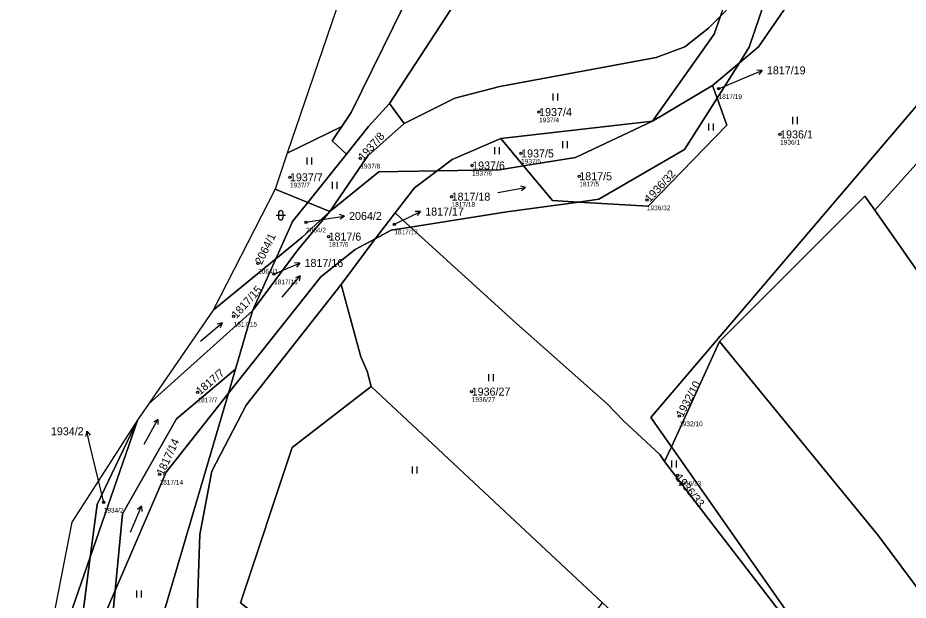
# Model space of a CAD drawing. Extents: x -762274 to -759271, y -1061928 to -1059060.
# Drawn here: x -761734.1 to -761545, y -1061234.6 to -1061110.9 of the extents above; entities that cross this region are included whole.
import ezdxf

# ---------------------------------------------------------------- set-up
doc = ezdxf.new("R2010")
doc.units = 0
for name, color, linetype in [('Definiční body', 7, 'Continuous'), ('Hranice parcel', 7, 'Continuous'), ('Parcelní čísla', 7, 'Continuous'), ('Polygon ku', 7, 'Continuous'), ('Polygon parcely', 7, 'Continuous'), ('Pop  PČ popisy', 7, 'Continuous'), ('Značky kultur', 7, 'Continuous')]:
    doc.layers.add(name, color=color, linetype=linetype)

msp = doc.modelspace()

# ---------------------------------------------------------------- linework, layer by layer
at = {"layer": 'Definiční body'}
for centre in [(-761585.27, -1061125.93), (-761623.37, -1061130.89), (-761572.19, -1061135.63), (-761627.19, -1061139.68), (-761661.33, -1061140.71), (-761637.59, -1061142.24), (-761676.28, -1061144.75), (-761614.84, -1061144.53), (-761641.96, -1061148.86), (-761600.48, -1061149.59), (-761672.86, -1061154.31), (-761654.12, -1061154.71), (-761668.09, -1061157.35), (-761683.05, -1061163.06), (-761679.65, -1061165.31), (-761688.24, -1061174.3), (-761695.91, -1061190.41), (-761637.69, -1061190.29), (-761593.62, -1061195.47), (-761703.97, -1061207.88), (-761593.93, -1061208.11), (-761715.84, -1061213.84)]:
    msp.add_circle(centre, 0.25, dxfattribs=at)
at = {"layer": 'Hranice parcel'}
for p, q in [((-761586.58, -1061125.23), (-761580.84, -1061120.41)), ((-761580.84, -1061120.41), (-761585.59, -1061127.93)), ((-761599.26, -1061132.85), (-761586.58, -1061125.23)), ((-761585.59, -1061127.93), (-761586.58, -1061125.23)), ((-761655.13, -1061129.07), (-761652.06, -1061133.33)), ((-761665.3, -1061133.96), (-761676.85, -1061139.64)), ((-761631.53, -1061136.51), (-761599.26, -1061132.85)), ((-761631.53, -1061136.51), (-761626.68, -1061142.32)), ((-761676.85, -1061139.64), (-761679.44, -1061147.26)), ((-761672.49, -1061150.08), (-761664.28, -1061139.8)), ((-761679.44, -1061147.26), (-761692.57, -1061172.96)), ((-761679.44, -1061147.26), (-761672.49, -1061150.08)), ((-761672.49, -1061150.08), (-761667.79, -1061151.98)), ((-761658.2, -1061157.81), (-761653.95, -1061152.32)), ((-761650.66, -1061155.32), (-761653.95, -1061152.32)), ((-761665.41, -1061167.51), (-761658.2, -1061157.81)), ((-761679.27, -1061162.04), (-761692.57, -1061172.96)), ((-761684.23, -1061173.13), (-761679.27, -1061162.04)), ((-761692.57, -1061172.96), (-761706.31, -1061192.95)), ((-761684.23, -1061173.13), (-761706.31, -1061192.95)), ((-761684.23, -1061173.13), (-761687.83, -1061185.51)), ((-761595.28, -1061201.99), (-761585.07, -1061179.66)), ((-761687.83, -1061185.51), (-761689.32, -1061190.63)), ((-761609.92, -1061235.2), (-761659.04, -1061189.22)), ((-761689.32, -1061190.63), (-761706.57, -1061248.98)), ((-761706.31, -1061192.95), (-761708.56, -1061196.23)), ((-761708.56, -1061196.23), (-761718.68, -1061225.44)), ((-761596.73, -1061205.16), (-761595.28, -1061201.99))]:
    msp.add_line(p, q, dxfattribs=at)
for points in [[(-761580.84, -1061120.41), (-761578.73, -1061117.07), (-761544.07, -1061015.12), (-761528.37, -1060979.24)], [(-761621.08, -1061016.62), (-761614.73, -1061021.75), (-761595.52, -1061037.25), (-761623.93, -1061081.12), (-761655.13, -1061129.07)], [(-761665.3, -1061133.96), (-761663.29, -1061130.97), (-761652.11, -1061108.27), (-761638.48, -1061080.32), (-761634.06, -1061069.21), (-761632.14, -1061061.04), (-761640.03, -1061045.99)], [(-761649.18, -1061061.93), (-761662.78, -1061098.32), (-761676.85, -1061139.64)], [(-761561.09, -1061083.11), (-761567.39, -1061101.46), (-761570.16, -1061107.4), (-761576.79, -1061117.01), (-761580.84, -1061120.41)], [(-761595.28, -1061201.99), (-761599.63, -1061195.76), (-761522.28, -1061104.91)], [(-761652.06, -1061133.33), (-761641.24, -1061127.91), (-761631.73, -1061125.43), (-761598.48, -1061119.29), (-761592.46, -1061117.03), (-761587.41, -1061113.06), (-761584.85, -1061110.5)], [(-761584.85, -1061110.5), (-761586.2, -1061114.32), (-761599.26, -1061132.85)], [(-761515.62, -1061111.21), (-761519.67, -1061115.58), (-761552.11, -1061151.74)], [(-761615.03, -1061150), (-761610.7, -1061149.4), (-761592.49, -1061138.84), (-761585.59, -1061127.93)], [(-761585.59, -1061127.93), (-761583.51, -1061133.64), (-761600.23, -1061150.87), (-761615.03, -1061150)], [(-761655.13, -1061129.07), (-761659.59, -1061133.93), (-761664.28, -1061139.8)], [(-761652.06, -1061133.33), (-761659.78, -1061140.16), (-761667.79, -1061151.98)], [(-761664.28, -1061139.8), (-761667.33, -1061136.97), (-761665.3, -1061133.96)], [(-761626.68, -1061142.32), (-761615.62, -1061140.51), (-761599.26, -1061132.85)], [(-761645.04, -1061143.39), (-761641.83, -1061140.97), (-761631.53, -1061136.51)], [(-761667.79, -1061151.98), (-761657.4, -1061143.6), (-761645.04, -1061143.39)], [(-761653.95, -1061152.32), (-761649.83, -1061147), (-761645.04, -1061143.39)], [(-761626.68, -1061142.32), (-761631.82, -1061143.16), (-761645.04, -1061143.39)], [(-761626.68, -1061142.32), (-761620.54, -1061149.68), (-761615.03, -1061150)], [(-761585.07, -1061179.66), (-761554.19, -1061148.78), (-761552.11, -1061151.74)], [(-761679.27, -1061162.04), (-761675.73, -1061154.14), (-761672.49, -1061150.08)], [(-761615.03, -1061150), (-761630.26, -1061152.12), (-761650.66, -1061155.32)], [(-761667.79, -1061151.98), (-761674.63, -1061160.17), (-761684.23, -1061173.13)], [(-761667.79, -1061151.98), (-761673.79, -1061157.55), (-761679.27, -1061162.04)], [(-761552.11, -1061151.74), (-761533.29, -1061178.58), (-761527.17, -1061188.33), (-761522.45, -1061195.71), (-761516.23, -1061206.21), (-761508.23, -1061218.1), (-761500.51, -1061231.41), (-761484.78, -1061257.45), (-761482.29, -1061263.15), (-761467.01, -1061292.02), (-761445.62, -1061345.22)], [(-761658.2, -1061157.81), (-761654.78, -1061155.96), (-761650.66, -1061155.32)], [(-761650.66, -1061155.32), (-761628.15, -1061175.84), (-761608.94, -1061192.88), (-761605.47, -1061196.5), (-761597.75, -1061203.66), (-761596.73, -1061205.16)], [(-761658.2, -1061157.81), (-761662.44, -1061160.1), (-761669.76, -1061165.89), (-761689.32, -1061190.63)], [(-761695.77, -1061297.85), (-761695.1, -1061291.96), (-761696.24, -1061245.59), (-761695.45, -1061220.62), (-761692.88, -1061207.19), (-761685.57, -1061193.15), (-761665.41, -1061167.51)], [(-761659.04, -1061189.22), (-761659.9, -1061185.97), (-761661.23, -1061182.91), (-761665.41, -1061167.51)], [(-761469.77, -1061348.28), (-761492.12, -1061311.82), (-761504.15, -1061292.16), (-761512.47, -1061277.76), (-761525.6, -1061256.54), (-761534.41, -1061243.67), (-761551.31, -1061220.9), (-761585.07, -1061179.66)], [(-761713.41, -1061232.57), (-761711.87, -1061216.24), (-761700.41, -1061196.07), (-761687.83, -1061185.51)], [(-761673.24, -1061303.98), (-761665.49, -1061299.29), (-761663.59, -1061285.01), (-761671.22, -1061246.54), (-761682.34, -1061238.64), (-761686.76, -1061235.2), (-761675.85, -1061202.17), (-761659.04, -1061189.22)], [(-761689.32, -1061190.63), (-761702.58, -1061207.4), (-761713.41, -1061232.57)], [(-761708.56, -1061196.23), (-761722.64, -1061218.01), (-761727.75, -1061244.52), (-761729.52, -1061273)], [(-761718.68, -1061225.44), (-761717.21, -1061214.29), (-761708.56, -1061196.23)], [(-761595.28, -1061201.99), (-761572, -1061235.34), (-761555.43, -1061258.99)], [(-761566.92, -1061243.95), (-761587.57, -1061217.19), (-761596.73, -1061205.16)], [(-761718.68, -1061225.44), (-761723.66, -1061239.8), (-761724.81, -1061251.78), (-761723.6, -1061273.04), (-761721.49, -1061290.2)], [(-761718.68, -1061225.44), (-761720.94, -1061242.51), (-761718.94, -1061287.87)], [(-761713.82, -1061272.87), (-761717.48, -1061251.72), (-761716.5, -1061239.74), (-761713.41, -1061232.57)], [(-761713.41, -1061232.57), (-761714.65, -1061245.65), (-761712.88, -1061270.1)]]:
    msp.add_lwpolyline(points, dxfattribs=at)
at = {"layer": 'Polygon ku'}
msp.add_lwpolyline([(-761662.78, -1061098.32), (-761676.85, -1061139.64), (-761679.44, -1061147.26), (-761692.57, -1061172.96), (-761706.31, -1061192.95), (-761708.56, -1061196.23), (-761722.64, -1061218.01), (-761727.75, -1061244.52)], dxfattribs=at)
at = {"layer": 'Polygon parcely'}
for points in [[(-761614.73, -1061021.75), (-761595.52, -1061037.25), (-761623.93, -1061081.12), (-761655.13, -1061129.07), (-761652.06, -1061133.33), (-761641.24, -1061127.91), (-761631.73, -1061125.43), (-761598.48, -1061119.29), (-761592.46, -1061117.03), (-761587.41, -1061113.06), (-761584.85, -1061110.5), (-761551.04, -1061014.93), (-761543.87, -1060996.64), (-761528.96, -1060950.6), (-761526.37, -1060946.41), (-761526.48, -1060946.18), (-761529.96, -1060939.02), (-761538.5, -1060955.71), (-761564.75, -1061008.67), (-761598.46, -1061007.56), (-761610.24, -1061007.17), (-761611.9, -1061007.12), (-761618.93, -1061013.71), (-761621.08, -1061016.62)], [(-761526.69, -1060981.53), (-761528.37, -1060979.24), (-761544.07, -1061015.12), (-761578.73, -1061117.07), (-761580.84, -1061120.41), (-761576.79, -1061117.01), (-761570.16, -1061107.4), (-761567.39, -1061101.46), (-761561.09, -1061083.11), (-761544.65, -1061035.26)], [(-761627.31, -1061025.05), (-761630.42, -1061029.26), (-761640.03, -1061045.99), (-761632.14, -1061061.04), (-761634.06, -1061069.21), (-761638.48, -1061080.32), (-761652.11, -1061108.27), (-761663.29, -1061130.97), (-761665.3, -1061133.96), (-761667.33, -1061136.97), (-761664.28, -1061139.8), (-761659.59, -1061133.93), (-761655.13, -1061129.07), (-761623.93, -1061081.12), (-761595.52, -1061037.25), (-761614.73, -1061021.75), (-761621.08, -1061016.62)], [(-761634.06, -1061069.21), (-761632.14, -1061061.04), (-761640.03, -1061045.99), (-761649.18, -1061061.93), (-761662.78, -1061098.32), (-761676.85, -1061139.64), (-761665.3, -1061133.96), (-761663.29, -1061130.97), (-761652.11, -1061108.27), (-761638.48, -1061080.32)], [(-761630.26, -1061152.12), (-761650.66, -1061155.32), (-761628.15, -1061175.84), (-761608.94, -1061192.88), (-761605.47, -1061196.5), (-761597.75, -1061203.66), (-761596.73, -1061205.16), (-761595.28, -1061201.99), (-761599.63, -1061195.76), (-761522.28, -1061104.91), (-761543.48, -1061091.91), (-761553.56, -1061086.48), (-761561.09, -1061083.11), (-761567.39, -1061101.46), (-761570.16, -1061107.4), (-761576.79, -1061117.01), (-761580.84, -1061120.41), (-761585.59, -1061127.93), (-761583.51, -1061133.64), (-761600.23, -1061150.87), (-761615.03, -1061150)], [(-761515.62, -1061111.21), (-761515.28, -1061110.5), (-761516.94, -1061108.19), (-761522.28, -1061104.91), (-761599.63, -1061195.76), (-761595.28, -1061201.99), (-761585.07, -1061179.66), (-761554.19, -1061148.78), (-761552.11, -1061151.74), (-761519.67, -1061115.58)], [(-761641.83, -1061140.97), (-761631.53, -1061136.51), (-761599.26, -1061132.85), (-761586.2, -1061114.32), (-761584.85, -1061110.5), (-761587.41, -1061113.06), (-761592.46, -1061117.03), (-761598.48, -1061119.29), (-761631.73, -1061125.43), (-761641.24, -1061127.91), (-761652.06, -1061133.33), (-761659.78, -1061140.16), (-761667.79, -1061151.98), (-761657.4, -1061143.6), (-761645.04, -1061143.39)], [(-761494.49, -1061147.79), (-761502.55, -1061133.44), (-761515.62, -1061111.21), (-761519.67, -1061115.58), (-761552.11, -1061151.74), (-761533.29, -1061178.58), (-761527.17, -1061188.33), (-761522.45, -1061195.71), (-761516.23, -1061206.21), (-761508.23, -1061218.1), (-761500.51, -1061231.41), (-761484.78, -1061257.45), (-761482.29, -1061263.15), (-761467.01, -1061292.02), (-761445.62, -1061345.22), (-761396.48, -1061329.97), (-761392.05, -1061338.2), (-761390.18, -1061337.94), (-761397.93, -1061322.85), (-761410.72, -1061299.74), (-761423.33, -1061276.18), (-761427.51, -1061269.02), (-761450.41, -1061226.12)], [(-761580.84, -1061120.41), (-761586.58, -1061125.23), (-761585.59, -1061127.93)], [(-761615.03, -1061150), (-761610.7, -1061149.4), (-761592.49, -1061138.84), (-761585.59, -1061127.93), (-761586.58, -1061125.23), (-761599.26, -1061132.85), (-761615.62, -1061140.51), (-761626.68, -1061142.32), (-761620.54, -1061149.68)], [(-761615.03, -1061150), (-761600.23, -1061150.87), (-761583.51, -1061133.64), (-761585.59, -1061127.93), (-761592.49, -1061138.84), (-761610.7, -1061149.4)], [(-761667.79, -1061151.98), (-761659.78, -1061140.16), (-761652.06, -1061133.33), (-761655.13, -1061129.07), (-761659.59, -1061133.93), (-761664.28, -1061139.8), (-761672.49, -1061150.08)], [(-761679.44, -1061147.26), (-761672.49, -1061150.08), (-761664.28, -1061139.8), (-761667.33, -1061136.97), (-761665.3, -1061133.96), (-761676.85, -1061139.64)], [(-761615.62, -1061140.51), (-761599.26, -1061132.85), (-761631.53, -1061136.51), (-761626.68, -1061142.32)], [(-761631.53, -1061136.51), (-761641.83, -1061140.97), (-761645.04, -1061143.39), (-761631.82, -1061143.16), (-761626.68, -1061142.32)], [(-761687.83, -1061185.51), (-761689.32, -1061190.63), (-761669.76, -1061165.89), (-761662.44, -1061160.1), (-761658.2, -1061157.81), (-761653.95, -1061152.32), (-761649.83, -1061147), (-761645.04, -1061143.39), (-761657.4, -1061143.6), (-761667.79, -1061151.98), (-761674.63, -1061160.17), (-761684.23, -1061173.13)], [(-761626.68, -1061142.32), (-761631.82, -1061143.16), (-761645.04, -1061143.39), (-761649.83, -1061147), (-761653.95, -1061152.32), (-761650.66, -1061155.32), (-761630.26, -1061152.12), (-761615.03, -1061150), (-761620.54, -1061149.68)], [(-761692.57, -1061172.96), (-761679.27, -1061162.04), (-761675.73, -1061154.14), (-761672.49, -1061150.08), (-761679.44, -1061147.26)], [(-761445.62, -1061345.22), (-761467.01, -1061292.02), (-761482.29, -1061263.15), (-761484.78, -1061257.45), (-761500.51, -1061231.41), (-761508.23, -1061218.1), (-761516.23, -1061206.21), (-761522.45, -1061195.71), (-761527.17, -1061188.33), (-761533.29, -1061178.58), (-761552.11, -1061151.74), (-761554.19, -1061148.78), (-761585.07, -1061179.66), (-761551.31, -1061220.9), (-761534.41, -1061243.67), (-761525.6, -1061256.54), (-761512.47, -1061277.76), (-761504.15, -1061292.16), (-761492.12, -1061311.82), (-761469.77, -1061348.28), (-761445.5, -1061345.53)], [(-761679.27, -1061162.04), (-761673.79, -1061157.55), (-761667.79, -1061151.98), (-761672.49, -1061150.08), (-761675.73, -1061154.14)], [(-761667.79, -1061151.98), (-761673.79, -1061157.55), (-761679.27, -1061162.04), (-761684.23, -1061173.13), (-761674.63, -1061160.17)], [(-761654.78, -1061155.96), (-761650.66, -1061155.32), (-761653.95, -1061152.32), (-761658.2, -1061157.81)], [(-761596.73, -1061205.16), (-761597.75, -1061203.66), (-761605.47, -1061196.5), (-761608.94, -1061192.88), (-761628.15, -1061175.84), (-761650.66, -1061155.32), (-761654.78, -1061155.96), (-761658.2, -1061157.81), (-761665.41, -1061167.51), (-761661.23, -1061182.91), (-761659.9, -1061185.97), (-761659.04, -1061189.22), (-761609.92, -1061235.2), (-761580.7, -1061262.1), (-761566.92, -1061243.95), (-761587.57, -1061217.19)], [(-761695.45, -1061220.62), (-761692.88, -1061207.19), (-761685.57, -1061193.15), (-761665.41, -1061167.51), (-761658.2, -1061157.81), (-761662.44, -1061160.1), (-761669.76, -1061165.89), (-761689.32, -1061190.63), (-761706.57, -1061248.98), (-761704.98, -1061278.4), (-761706.17, -1061295.02), (-761709.24, -1061312.83), (-761713.97, -1061323.22), (-761716.95, -1061341.7), (-761724.88, -1061363.45), (-761722.53, -1061366.14), (-761701.27, -1061325.5), (-761696.94, -1061307.26), (-761695.77, -1061297.85), (-761695.1, -1061291.96), (-761696.24, -1061245.59)], [(-761706.31, -1061192.95), (-761684.23, -1061173.13), (-761679.27, -1061162.04), (-761692.57, -1061172.96)], [(-761665.49, -1061299.29), (-761663.59, -1061285.01), (-761671.22, -1061246.54), (-761682.34, -1061238.64), (-761686.76, -1061235.2), (-761675.85, -1061202.17), (-761659.04, -1061189.22), (-761659.9, -1061185.97), (-761661.23, -1061182.91), (-761665.41, -1061167.51), (-761685.57, -1061193.15), (-761692.88, -1061207.19), (-761695.45, -1061220.62), (-761696.24, -1061245.59), (-761695.1, -1061291.96), (-761695.77, -1061297.85), (-761673.24, -1061303.98)], [(-761708.56, -1061196.23), (-761718.68, -1061225.44), (-761720.94, -1061242.51), (-761718.94, -1061287.87), (-761713.82, -1061272.87), (-761717.48, -1061251.72), (-761716.5, -1061239.74), (-761713.41, -1061232.57), (-761711.87, -1061216.24), (-761700.41, -1061196.07), (-761687.83, -1061185.51), (-761684.23, -1061173.13), (-761706.31, -1061192.95)], [(-761555.43, -1061258.99), (-761540, -1061279.71), (-761519.07, -1061308.54), (-761497.82, -1061338.46), (-761488.71, -1061351.23), (-761469.77, -1061348.28), (-761492.12, -1061311.82), (-761504.15, -1061292.16), (-761512.47, -1061277.76), (-761525.6, -1061256.54), (-761534.41, -1061243.67), (-761551.31, -1061220.9), (-761585.07, -1061179.66), (-761595.28, -1061201.99), (-761572, -1061235.34)], [(-761713.41, -1061232.57), (-761702.58, -1061207.4), (-761689.32, -1061190.63), (-761687.83, -1061185.51), (-761700.41, -1061196.07), (-761711.87, -1061216.24)], [(-761609.92, -1061235.2), (-761659.04, -1061189.22), (-761675.85, -1061202.17), (-761686.76, -1061235.2), (-761682.34, -1061238.64), (-761671.22, -1061246.54), (-761663.59, -1061285.01), (-761665.49, -1061299.29), (-761673.24, -1061303.98), (-761680.44, -1061309.11), (-761660.29, -1061328.83), (-761655.36, -1061301.96), (-761657.85, -1061281.76), (-761658.92, -1061262.63), (-761637.58, -1061272.31), (-761636.9, -1061273.42), (-761634.56, -1061270.16), (-761622.18, -1061250.92)], [(-761706.57, -1061248.98), (-761689.32, -1061190.63), (-761702.58, -1061207.4), (-761713.41, -1061232.57), (-761714.65, -1061245.65), (-761712.88, -1061270.1), (-761712.8, -1061269.86)], [(-761729.52, -1061273), (-761734.08, -1061288.46), (-761721.49, -1061290.2), (-761723.6, -1061273.04), (-761724.81, -1061251.78), (-761723.66, -1061239.8), (-761718.68, -1061225.44), (-761717.21, -1061214.29), (-761708.56, -1061196.23), (-761722.64, -1061218.01), (-761727.75, -1061244.52)], [(-761708.56, -1061196.23), (-761717.21, -1061214.29), (-761718.68, -1061225.44)], [(-761555.43, -1061258.99), (-761572, -1061235.34), (-761595.28, -1061201.99), (-761596.73, -1061205.16), (-761587.57, -1061217.19), (-761566.92, -1061243.95)], [(-761718.68, -1061225.44), (-761723.66, -1061239.8), (-761724.81, -1061251.78), (-761723.6, -1061273.04), (-761721.49, -1061290.2), (-761721.08, -1061293.93), (-761718.94, -1061287.87), (-761720.94, -1061242.51)], [(-761712.88, -1061270.1), (-761714.65, -1061245.65), (-761713.41, -1061232.57), (-761716.5, -1061239.74), (-761717.48, -1061251.72), (-761713.82, -1061272.87)]]:
    msp.add_lwpolyline(points, close=True, dxfattribs=at)
msp.add_lwpolyline([(-761543.87, -1060996.64), (-761561.28, -1061052.99), (-761575.72, -1061096.53), (-761580.18, -1061105.64), (-761584.85, -1061110.5), (-761586.2, -1061114.32), (-761599.26, -1061132.85), (-761586.58, -1061125.23), (-761580.84, -1061120.41), (-761578.73, -1061117.07), (-761544.07, -1061015.12)], dxfattribs=at)
at = {"layer": 'Pop  PČ popisy'}
for p, q in [((-761585.27, -1061125.93), (-761578.76, -1061123.19)), ((-761578.76, -1061123.19), (-761576, -1061122.02)), ((-761576, -1061122.02), (-761577.11, -1061121.95)), ((-761576, -1061122.02), (-761576.72, -1061122.87)), ((-761672.86, -1061154.31), (-761667.69, -1061153.46)), ((-761667.69, -1061153.46), (-761664.73, -1061152.99)), ((-761664.73, -1061152.99), (-761665.79, -1061152.65)), ((-761664.73, -1061152.99), (-761665.64, -1061153.64)), ((-761654.12, -1061154.71), (-761651.26, -1061153.33)), ((-761651.26, -1061153.33), (-761648.56, -1061152.01)), ((-761648.56, -1061152.01), (-761649.68, -1061152)), ((-761648.56, -1061152.01), (-761649.24, -1061152.9)), ((-761676.94, -1061164.14), (-761674.18, -1061162.97)), ((-761674.18, -1061162.97), (-761675.3, -1061162.9)), ((-761674.18, -1061162.97), (-761674.9, -1061163.82)), ((-761679.65, -1061165.31), (-761676.94, -1061164.14)), ((-761719.43, -1061198.71), (-761719.69, -1061199.79)), ((-761718.75, -1061201.63), (-761719.43, -1061198.71)), ((-761719.43, -1061198.71), (-761718.71, -1061199.57)), ((-761715.84, -1061213.84), (-761718.75, -1061201.63))]:
    msp.add_line(p, q, dxfattribs=at)
at = {"layer": 'Značky kultur'}
for p, q in [((-761620.42, -1061128.44), (-761620.42, -1061126.94)), ((-761619.42, -1061128.44), (-761619.42, -1061126.94)), ((-761569.5, -1061133.43), (-761569.5, -1061131.93)), ((-761568.5, -1061133.43), (-761568.5, -1061131.93)), ((-761587.32, -1061134.81), (-761587.32, -1061133.31)), ((-761586.32, -1061134.81), (-761586.32, -1061133.31)), ((-761632.77, -1061139.84), (-761632.77, -1061138.34)), ((-761631.77, -1061139.84), (-761631.77, -1061138.34)), ((-761618.34, -1061138.58), (-761618.34, -1061137.08)), ((-761617.34, -1061138.58), (-761617.34, -1061137.08)), ((-761672.63, -1061142.03), (-761672.63, -1061140.53)), ((-761671.63, -1061142.03), (-761671.63, -1061140.53)), ((-761667.26, -1061147.23), (-761667.26, -1061145.73)), ((-761666.26, -1061147.23), (-761666.26, -1061145.73)), ((-761632.14, -1061147.98), (-761626.23, -1061146.94)), ((-761626.23, -1061146.94), (-761627.28, -1061146.61)), ((-761626.23, -1061146.94), (-761627.1, -1061147.6)), ((-761679.24, -1061152.82), (-761677.24, -1061152.82)), ((-761678.74, -1061152.32), (-761678.74, -1061153.32)), ((-761677.74, -1061153.32), (-761677.74, -1061152.32)), ((-761677.97, -1061170.25), (-761674.11, -1061165.65)), ((-761674.11, -1061165.65), (-761675.13, -1061166.08)), ((-761674.11, -1061165.65), (-761674.36, -1061166.73)), ((-761695.28, -1061179.54), (-761690.68, -1061175.69)), ((-761690.68, -1061175.69), (-761691.75, -1061175.93)), ((-761690.68, -1061175.69), (-761691.11, -1061176.7)), ((-761634.06, -1061188.09), (-761634.06, -1061186.59)), ((-761633.06, -1061188.09), (-761633.06, -1061186.59)), ((-761707.22, -1061201.42), (-761704.31, -1061196.18)), ((-761704.31, -1061196.18), (-761705.22, -1061196.79)), ((-761704.31, -1061196.18), (-761704.34, -1061197.27)), ((-761650.27, -1061207.7), (-761650.27, -1061206.2)), ((-761649.27, -1061207.7), (-761649.27, -1061206.2)), ((-761595.19, -1061206.42), (-761595.19, -1061204.92)), ((-761594.19, -1061206.42), (-761594.19, -1061204.92)), ((-761710.15, -1061220.18), (-761707.8, -1061214.66)), ((-761707.8, -1061214.66), (-761708.65, -1061215.36)), ((-761707.8, -1061214.66), (-761707.72, -1061215.75)), ((-761708.82, -1061234.02), (-761708.82, -1061232.52)), ((-761707.82, -1061234.02), (-761707.82, -1061232.52))]:
    msp.add_line(p, q, dxfattribs=at)
for centre, start, end in [((-761678.24, -1061152.32), 0, 180), ((-761678.24, -1061153.32), 180, 359.9879)]:
    msp.add_arc(centre, 0.5, start, end, dxfattribs=at)

# ---------------------------------------------------------------- texts
at = {"layer": 'Definiční body'}
for s, p in [('1817/19', (-761585.27, -1061128.09)), ('1937/4', (-761623.37, -1061133.05)), ('1936/1', (-761572.19, -1061137.79)), ('1937/8', (-761661.33, -1061142.87)), ('1937/5', (-761627.19, -1061141.84)), ('1937/6', (-761637.59, -1061144.4)), ('1937/7', (-761676.28, -1061146.91)), ('1817/5', (-761614.84, -1061146.69)), ('1817/18', (-761641.96, -1061151.02)), ('1936/32', (-761600.48, -1061151.75)), ('2064/2', (-761672.86, -1061156.47)), ('1817/17', (-761654.12, -1061156.87)), ('1817/6', (-761668.09, -1061159.51)), ('2064/1', (-761683.05, -1061165.22)), ('1817/16', (-761679.65, -1061167.47)), ('1817/15', (-761688.24, -1061176.46)), ('1817/7', (-761695.91, -1061192.57)), ('1936/27', (-761637.69, -1061192.45)), ('1932/10', (-761593.62, -1061197.63)), ('1817/14', (-761703.97, -1061210.04)), ('1936/33', (-761593.93, -1061210.27)), ('1934/2', (-761715.84, -1061216))]:
    msp.add_text(s, height=1, dxfattribs=at).set_placement(p)
at = {"layer": 'Parcelní čísla'}
for s, p in [('1817/19', (-761575, -1061122.87)), ('1937/4', (-761623.37, -1061131.74)), ('1936/1', (-761572.19, -1061136.48)), ('1937/5', (-761627.19, -1061140.53)), ('1937/6', (-761637.59, -1061143.09)), ('1937/7', (-761676.28, -1061145.6)), ('1817/5', (-761614.84, -1061145.38)), ('1817/18', (-761641.96, -1061149.71)), ('1817/17', (-761647.56, -1061152.88)), ('2064/2', (-761663.73, -1061153.82)), ('1817/6', (-761668.09, -1061158.2)), ('1817/16', (-761673.19, -1061163.8)), ('1936/27', (-761637.69, -1061191.14)), ('1934/2', (-761727.05, -1061199.56))]:
    msp.add_text(s, height=1.7, dxfattribs=at).set_placement(p)
for s, rotation, p in [('1937/8', 48, (-761660.7, -1061141.28)), ('1936/32', 47, (-761599.86, -1061150.17)), ('2064/1', 64, (-761682.29, -1061163.43)), ('1817/15', 48, (-761687.61, -1061174.87)), ('1817/7', 40, (-761695.36, -1061191.06)), ('1932/10', 62, (-761592.87, -1061195.87)), ('1817/14', 65, (-761703.2, -1061208.24)), ('1936/33', 309, (-761594.59, -1061208.64))]:
    msp.add_text(s, height=1.7, rotation=rotation, dxfattribs=at).set_placement(p)

doc.saveas('drawing.dxf')
